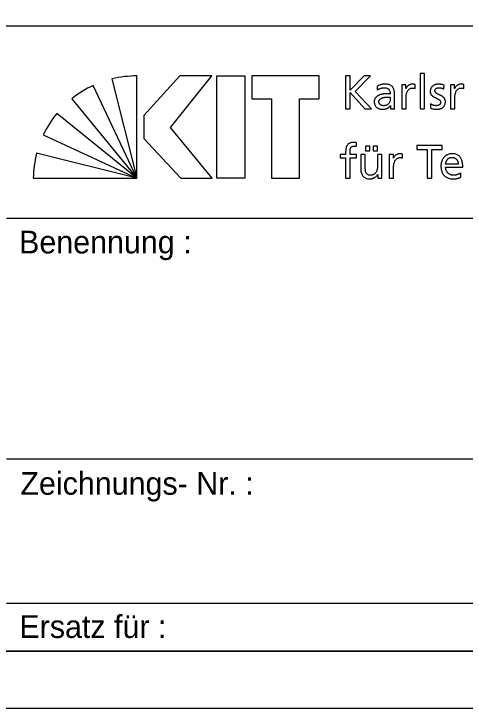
# Model space of a CAD drawing. Extents: x 0 to 29.7, y 0 to 21.
# Drawn here: x 27.516 to 28.508, y 0 to 1.526 of the extents above; entities that cross this region are included whole.
import ezdxf

# ---------------------------------------------------------------- set-up
doc = ezdxf.new("R2010")
doc.units = 0
doc.layers.add('90_Plankopf', color=7, linetype='Continuous')

msp = doc.modelspace()

# ---------------------------------------------------------------- linework, layer by layer
at = {"layer": '90_Plankopf'}
for p, q in [((25.153, 1.4998), (29.6, 1.4998)), ((25.153, 1.4998), (29.6, 1.4998)), ((27.787, 1.1647), (27.787, 1.3896)), ((28.2452, 1.3897), (28.2452, 1.3176)), ((27.7319, 1.3833), (27.787, 1.1647)), ((27.787, 1.1647), (27.6908, 1.3688)), ((28.3145, 1.3665), (28.315, 1.3583)), ((28.3982, 1.3621), (28.3982, 1.3708)), ((28.4614, 1.361), (28.4622, 1.3694)), ((28.5053, 1.3621), (28.5053, 1.3708)), ((28.353, 1.328), (28.353, 1.3497)), ((27.6436, 1.3396), (27.787, 1.1647)), ((28.3433, 1.3427), (28.3433, 1.3381)), ((28.4324, 1.328), (28.4319, 1.3193)), ((28.2452, 1.3176), (28.2556, 1.3176)), ((28.2876, 1.3176), (28.3027, 1.3176)), ((27.787, 1.1647), (27.6108, 1.3071)), ((27.581, 1.2603), (27.787, 1.1647)), ((28.2693, 1.2348), (28.2697, 1.2427)), ((27.787, 1.1647), (27.5664, 1.2197)), ((28.3707, 1.2091), (28.3707, 1.2178)), ((28.4927, 1.196), (28.4654, 1.196)), ((28.4654, 1.1888), (28.503, 1.1888)), ((28.4989, 1.1668), (28.4989, 1.1765)), ((27.5591, 1.1647), (27.787, 1.1647)), ((27.5, 1.0768), (29.6, 1.0768)), ((27.5, 0.548), (29.6, 0.548)), ((27.5, 0.2308), (29.6, 0.2308)), ((29.6, 0.125), (25.153, 0.125)), ((25.445, 0.125), (29.6, 0.125)), ((25.445, 0.125), (29.6, 0.125))]:
    msp.add_line(p, q, dxfattribs=at)
for points in [[(0, 0), (29.725, 0), (29.725, 21.025), (0, 21.025)], [(0.625, 0.125), (29.6, 0.125), (29.6, 20.9), (0.625, 20.9)], [(27.9517, 1.3897), (27.8809, 1.3897), (27.8018, 1.3025), (27.8018, 1.2523), (27.8834, 1.1647), (27.9521, 1.1647), (27.8606, 1.2766)], [(28.0243, 1.3897), (28.0243, 1.1647), (27.9625, 1.1647), (27.9625, 1.3897)], [(28.0391, 1.3897), (28.0391, 1.339), (28.0825, 1.339), (28.0825, 1.1647), (28.1443, 1.1647), (28.1443, 1.339), (28.1877, 1.339), (28.1877, 1.3897)]]:
    msp.add_lwpolyline(points, close=True, dxfattribs=at)
for points in [[(28.3027, 1.3176), (28.2662, 1.3556), (28.3, 1.3897), (28.2863, 1.3897), (28.2556, 1.358), (28.2556, 1.3897), (28.2452, 1.3897)], [(28.4095, 1.3176), (28.4192, 1.3176), (28.4192, 1.395), (28.4095, 1.395), (28.4095, 1.3176)], [(28.378, 1.3621), (28.3778, 1.3621), (28.3778, 1.3703), (28.3688, 1.3703), (28.3688, 1.3176), (28.3785, 1.3176), (28.3785, 1.3416)], [(28.4852, 1.3621), (28.485, 1.3621), (28.485, 1.3703), (28.4759, 1.3703), (28.4759, 1.3176), (28.4856, 1.3176), (28.4856, 1.3416)], [(28.2556, 1.3176), (28.2556, 1.3529), (28.2876, 1.3176)], [(28.3441, 1.3245), (28.3443, 1.3245), (28.3443, 1.3176), (28.3534, 1.3176)], [(28.4248, 1.1647), (28.4351, 1.1647), (28.4351, 1.2276), (28.4575, 1.2276), (28.4575, 1.2367), (28.4024, 1.2367), (28.4024, 1.2276), (28.4248, 1.2276), (28.4248, 1.1647)], [(28.2456, 1.2221), (28.2456, 1.2173), (28.2332, 1.2173), (28.2332, 1.2094), (28.2456, 1.2094), (28.2456, 1.1647), (28.2553, 1.1647), (28.2553, 1.2094), (28.2692, 1.2094), (28.2692, 1.2173), (28.2553, 1.2173), (28.2553, 1.223)], [(28.2889, 1.2356), (28.2889, 1.2253), (28.2986, 1.2253), (28.2986, 1.2356), (28.2889, 1.2356)], [(28.3058, 1.2356), (28.3058, 1.2253), (28.3155, 1.2253), (28.3155, 1.2356), (28.3058, 1.2356)], [(28.2885, 1.19), (28.2885, 1.2173), (28.2788, 1.2173), (28.2788, 1.186)], [(28.3254, 1.1647), (28.3254, 1.2173), (28.3157, 1.2173), (28.3157, 1.1929)], [(28.3506, 1.2091), (28.3504, 1.2091), (28.3504, 1.2173), (28.3413, 1.2173), (28.3413, 1.1647), (28.351, 1.1647), (28.351, 1.1886)], [(28.3158, 1.173), (28.316, 1.173), (28.316, 1.1647), (28.3254, 1.1647)]]:
    msp.add_lwpolyline(points, dxfattribs=at)
for centre, start, end in [((27.7862, 1.1514), 89.8053, 103.1895), ((27.7915, 1.1529), 115.0126, 128.3968), ((27.7954, 1.1566), 140.7898, 154.174), ((27.7973, 1.1609), 165.7222, 179.1064)]:
    msp.add_arc(centre, 0.2382, start, end, dxfattribs=at)
for points in [[(28.353, 1.3497), (28.353, 1.3545), (28.3523, 1.3585), (28.3508, 1.3617), (28.3494, 1.365), (28.3471, 1.3674), (28.344, 1.369), (28.3409, 1.3707), (28.3368, 1.3715), (28.3318, 1.3715), (28.3285, 1.3715), (28.3253, 1.371), (28.3224, 1.3701), (28.3195, 1.3692), (28.3169, 1.368), (28.3145, 1.3665)], [(28.315, 1.3583), (28.3163, 1.3594), (28.3178, 1.3604), (28.3195, 1.3611), (28.3211, 1.362), (28.3229, 1.3626), (28.3247, 1.363), (28.3266, 1.3634), (28.3284, 1.3637), (28.3303, 1.3637), (28.3335, 1.3637), (28.336, 1.3631), (28.3379, 1.3621), (28.3399, 1.3611), (28.3412, 1.3596), (28.342, 1.3575), (28.3429, 1.3555), (28.3433, 1.353), (28.3433, 1.3499)], [(28.3982, 1.3708), (28.3975, 1.3709), (28.3968, 1.371), (28.3962, 1.3712), (28.3956, 1.3713), (28.3949, 1.3713), (28.3942, 1.3714), (28.3935, 1.3715), (28.3927, 1.3715), (28.3918, 1.3715), (28.3899, 1.3715), (28.3881, 1.3711), (28.3863, 1.3703), (28.3845, 1.3695), (28.3829, 1.3684), (28.3815, 1.367), (28.3801, 1.3656), (28.3789, 1.3639), (28.378, 1.3621)], [(28.3785, 1.3416), (28.3785, 1.346), (28.3791, 1.3498), (28.3802, 1.353), (28.3814, 1.3562), (28.3831, 1.3587), (28.3852, 1.3604), (28.3874, 1.3621), (28.3899, 1.363), (28.3928, 1.363), (28.3936, 1.3631), (28.3945, 1.363), (28.3954, 1.3629), (28.3964, 1.3627), (28.3973, 1.3625), (28.3982, 1.3621)], [(28.4622, 1.3694), (28.4604, 1.37), (28.4584, 1.3705), (28.4565, 1.3709), (28.4545, 1.3713), (28.4524, 1.3715), (28.4502, 1.3715), (28.4476, 1.3715), (28.4451, 1.3712), (28.4429, 1.3705), (28.4406, 1.3698), (28.4387, 1.3688), (28.437, 1.3675), (28.4353, 1.3662), (28.434, 1.3645), (28.433, 1.3625), (28.4321, 1.3604), (28.4316, 1.358), (28.4316, 1.3553), (28.4316, 1.3532), (28.4321, 1.3514), (28.4329, 1.3498), (28.4337, 1.3483), (28.4348, 1.347), (28.4361, 1.3459), (28.4375, 1.3447), (28.439, 1.3437), (28.4406, 1.3429), (28.4422, 1.342), (28.4438, 1.3412), (28.4454, 1.3404), (28.4471, 1.3397), (28.4485, 1.3389), (28.4499, 1.338), (28.4512, 1.3373), (28.4523, 1.3363), (28.4532, 1.3353), (28.454, 1.3343), (28.4544, 1.3331), (28.4544, 1.3318), (28.4544, 1.3304), (28.4541, 1.3292), (28.4535, 1.3282), (28.4529, 1.3272), (28.4521, 1.3265), (28.4511, 1.3259), (28.4501, 1.3253), (28.4491, 1.3249), (28.4479, 1.3246), (28.4468, 1.3244), (28.4456, 1.3242), (28.4445, 1.3242), (28.4435, 1.3242), (28.4424, 1.3244), (28.441, 1.3247), (28.4396, 1.3249), (28.4381, 1.3253), (28.4366, 1.3259), (28.4351, 1.3265), (28.4337, 1.3271), (28.4324, 1.328)], [(28.4319, 1.3193), (28.4342, 1.3181), (28.4365, 1.3174), (28.4389, 1.317), (28.4414, 1.3166), (28.4439, 1.3164), (28.4464, 1.3164), (28.4487, 1.3164), (28.451, 1.3167), (28.4532, 1.3174), (28.4554, 1.318), (28.4573, 1.3191), (28.4591, 1.3204), (28.4608, 1.3217), (28.4622, 1.3234), (28.4632, 1.3255), (28.4642, 1.3276), (28.4647, 1.33), (28.4647, 1.3328), (28.4647, 1.3352), (28.4643, 1.3372), (28.4635, 1.3389), (28.4626, 1.3406), (28.4616, 1.342), (28.4602, 1.3431), (28.4589, 1.3443), (28.4574, 1.3453), (28.4557, 1.3461), (28.4541, 1.3469), (28.4525, 1.3477), (28.4509, 1.3484), (28.4493, 1.3491), (28.4478, 1.3499), (28.4464, 1.3507), (28.4451, 1.3515), (28.444, 1.3524), (28.4432, 1.3534), (28.4424, 1.3545), (28.4419, 1.3557), (28.4419, 1.3573), (28.4419, 1.3587), (28.4424, 1.3599), (28.4432, 1.3609), (28.4441, 1.3618), (28.4452, 1.3625), (28.4466, 1.363), (28.448, 1.3634), (28.4495, 1.3637), (28.4512, 1.3637), (28.4518, 1.3637), (28.4526, 1.3636), (28.4535, 1.3634), (28.4544, 1.3633), (28.4553, 1.3631), (28.4564, 1.3628), (28.4574, 1.3626), (28.4583, 1.3623), (28.4592, 1.362), (28.4601, 1.3616), (28.4609, 1.3613), (28.4614, 1.361)], [(28.5053, 1.3708), (28.5046, 1.3709), (28.504, 1.371), (28.5034, 1.3712), (28.5027, 1.3713), (28.5021, 1.3713), (28.5014, 1.3714), (28.5007, 1.3715), (28.4998, 1.3715), (28.4989, 1.3715), (28.497, 1.3715), (28.4952, 1.3711), (28.4934, 1.3703), (28.4917, 1.3695), (28.4901, 1.3684), (28.4886, 1.367), (28.4872, 1.3656), (28.486, 1.3639), (28.4852, 1.3621)], [(28.4856, 1.3416), (28.4856, 1.346), (28.4862, 1.3498), (28.4874, 1.353), (28.4886, 1.3562), (28.4902, 1.3587), (28.4923, 1.3604), (28.4945, 1.3621), (28.497, 1.363), (28.4999, 1.363), (28.5008, 1.3631), (28.5016, 1.363), (28.5026, 1.3629), (28.5035, 1.3627), (28.5044, 1.3625), (28.5053, 1.3621)], [(28.3433, 1.3499), (28.342, 1.35), (28.3408, 1.3501), (28.3397, 1.3501), (28.3386, 1.3501), (28.3376, 1.3501), (28.3365, 1.3501), (28.3354, 1.3501), (28.3342, 1.3501), (28.3329, 1.3501), (28.3309, 1.3501), (28.3288, 1.35), (28.3266, 1.3496), (28.3243, 1.3492), (28.3221, 1.3487), (28.32, 1.3478), (28.3179, 1.347), (28.316, 1.346), (28.3142, 1.3446), (28.3125, 1.3433), (28.3111, 1.3416), (28.3101, 1.3397), (28.309, 1.3377), (28.3085, 1.3354), (28.3085, 1.3328), (28.3085, 1.329), (28.3094, 1.3259), (28.311, 1.3235), (28.3126, 1.3211), (28.3149, 1.3193), (28.3177, 1.3181), (28.3206, 1.317), (28.324, 1.3164), (28.3278, 1.3164), (28.33, 1.3164), (28.332, 1.3167), (28.3338, 1.3172), (28.3355, 1.3177), (28.3371, 1.3184), (28.3384, 1.3192), (28.3398, 1.32), (28.3409, 1.3209), (28.3418, 1.3218), (28.3428, 1.3228), (28.3435, 1.3236), (28.3441, 1.3245)], [(28.3433, 1.3381), (28.3433, 1.3354), (28.3427, 1.3331), (28.3416, 1.331), (28.3405, 1.3289), (28.3388, 1.3273), (28.3367, 1.3261), (28.3345, 1.3249), (28.3318, 1.3243), (28.3286, 1.3242), (28.3275, 1.3242), (28.3264, 1.3244), (28.3252, 1.3248), (28.3241, 1.3252), (28.323, 1.3257), (28.322, 1.3264), (28.3211, 1.3272), (28.3203, 1.3281), (28.3197, 1.3291), (28.3191, 1.3302), (28.3188, 1.3314), (28.3188, 1.3328), (28.3188, 1.3347), (28.3193, 1.3362), (28.3202, 1.3374), (28.3211, 1.3387), (28.3223, 1.3396), (28.3237, 1.3404), (28.3252, 1.3411), (28.3267, 1.3417), (28.3284, 1.342), (28.33, 1.3424), (28.3316, 1.3426), (28.3332, 1.3428), (28.3347, 1.3429), (28.336, 1.3429), (28.3371, 1.3429), (28.3381, 1.3429), (28.3391, 1.3429), (28.3402, 1.3428), (28.3412, 1.3428), (28.3422, 1.3427), (28.3433, 1.3427)], [(28.3534, 1.3176), (28.3533, 1.3181), (28.3532, 1.3188), (28.3532, 1.3197), (28.3531, 1.3205), (28.3531, 1.3216), (28.353, 1.323), (28.353, 1.3243), (28.353, 1.326), (28.353, 1.328)], [(28.2697, 1.2427), (28.2688, 1.2428), (28.2678, 1.243), (28.2667, 1.2431), (28.2656, 1.2432), (28.2645, 1.2433), (28.2632, 1.2433), (28.2597, 1.2433), (28.2568, 1.2428), (28.2544, 1.2418), (28.2521, 1.2408), (28.2503, 1.2394), (28.2491, 1.2375), (28.2478, 1.2356), (28.2469, 1.2334), (28.2464, 1.2308), (28.2458, 1.2282), (28.2456, 1.2253), (28.2456, 1.2221)], [(28.2553, 1.223), (28.2553, 1.2247), (28.2554, 1.2264), (28.2556, 1.2279), (28.2558, 1.2294), (28.2562, 1.2307), (28.2569, 1.2319), (28.2575, 1.233), (28.2585, 1.2339), (28.2597, 1.2345), (28.261, 1.2351), (28.2626, 1.2354), (28.2647, 1.2354), (28.2655, 1.2354), (28.2664, 1.2354), (28.2672, 1.2353), (28.268, 1.2352), (28.2688, 1.235), (28.2693, 1.2348)], [(28.3707, 1.2178), (28.37, 1.2179), (28.3693, 1.2181), (28.3688, 1.2182), (28.3681, 1.2183), (28.3675, 1.2184), (28.3667, 1.2184), (28.3661, 1.2185), (28.3652, 1.2185), (28.3643, 1.2185), (28.3624, 1.2185), (28.3606, 1.2181), (28.3588, 1.2173), (28.3571, 1.2165), (28.3555, 1.2154), (28.354, 1.214), (28.3526, 1.2126), (28.3514, 1.211), (28.3506, 1.2091)], [(28.351, 1.1886), (28.351, 1.193), (28.3516, 1.1968), (28.3528, 1.2), (28.3539, 1.2032), (28.3556, 1.2057), (28.3577, 1.2074), (28.3599, 1.2092), (28.3624, 1.21), (28.3653, 1.21), (28.3662, 1.2101), (28.367, 1.21), (28.368, 1.2099), (28.3689, 1.2097), (28.3698, 1.2095), (28.3707, 1.2091)], [(28.503, 1.1888), (28.503, 1.1931), (28.5026, 1.197), (28.5018, 1.2006), (28.501, 1.2042), (28.4997, 1.2073), (28.4979, 1.21), (28.4961, 1.2127), (28.4938, 1.2148), (28.4908, 1.2162), (28.4878, 1.2177), (28.4841, 1.2185), (28.4797, 1.2185), (28.476, 1.2185), (28.4726, 1.2178), (28.4696, 1.2166), (28.4666, 1.2152), (28.464, 1.2134), (28.4618, 1.2111), (28.4597, 1.2087), (28.458, 1.2059), (28.4569, 1.2026), (28.4557, 1.1994), (28.4551, 1.1958), (28.4551, 1.1919), (28.4551, 1.1876), (28.4556, 1.1837), (28.4567, 1.1802), (28.4578, 1.1767), (28.4595, 1.1737), (28.4617, 1.1712), (28.4639, 1.1687), (28.4668, 1.1668), (28.4702, 1.1655), (28.4736, 1.1641), (28.4777, 1.1634), (28.4823, 1.1634), (28.4852, 1.1634), (28.4876, 1.1636), (28.4897, 1.164), (28.4917, 1.1644), (28.4934, 1.1648), (28.4949, 1.1653), (28.4964, 1.1659), (28.4977, 1.1664), (28.4989, 1.1668)], [(28.4654, 1.196), (28.4656, 1.1977), (28.466, 1.1995), (28.4666, 1.2012), (28.4672, 1.2029), (28.4681, 1.2045), (28.4692, 1.2059), (28.4703, 1.2073), (28.4717, 1.2085), (28.4734, 1.2093), (28.4751, 1.2102), (28.4772, 1.2107), (28.4795, 1.2107), (28.4816, 1.2107), (28.4835, 1.2103), (28.4851, 1.2095), (28.4867, 1.2088), (28.4881, 1.2077), (28.4892, 1.2064), (28.4903, 1.205), (28.4912, 1.2035), (28.4918, 1.2017), (28.4924, 1.1999), (28.4927, 1.1981), (28.4927, 1.196)], [(28.3157, 1.1929), (28.3157, 1.1897), (28.3154, 1.1868), (28.3147, 1.1841), (28.3141, 1.1815), (28.3131, 1.1792), (28.3118, 1.1773), (28.3105, 1.1754), (28.3088, 1.1739), (28.3068, 1.1728), (28.3048, 1.1718), (28.3024, 1.1713), (28.2997, 1.1713), (28.2969, 1.1714), (28.2947, 1.1722), (28.293, 1.1736), (28.2914, 1.175), (28.2902, 1.1771), (28.2895, 1.1798), (28.2889, 1.1825), (28.2885, 1.1859), (28.2885, 1.19)], [(28.2788, 1.186), (28.2788, 1.1813), (28.2795, 1.1772), (28.2809, 1.1739), (28.2823, 1.1705), (28.2845, 1.1679), (28.2874, 1.1661), (28.2903, 1.1644), (28.294, 1.1634), (28.2986, 1.1634), (28.301, 1.1634), (28.3034, 1.1638), (28.3056, 1.1646), (28.3079, 1.1653), (28.3099, 1.1665), (28.3117, 1.1679), (28.3134, 1.1693), (28.3148, 1.171), (28.3158, 1.173)], [(28.4989, 1.1765), (28.4983, 1.176), (28.4975, 1.1755), (28.4963, 1.1749), (28.4952, 1.1743), (28.4939, 1.1737), (28.4924, 1.1732), (28.4909, 1.1726), (28.4893, 1.1722), (28.4876, 1.1718), (28.486, 1.1715), (28.4844, 1.1713), (28.4827, 1.1713), (28.4804, 1.1713), (28.4782, 1.1717), (28.4762, 1.1725), (28.4741, 1.1734), (28.4722, 1.1746), (28.4706, 1.1761), (28.469, 1.1777), (28.4677, 1.1795), (28.4668, 1.1817), (28.4659, 1.1838), (28.4654, 1.1862), (28.4654, 1.1888)]]:
    msp.add_open_spline(points, degree=3, dxfattribs=at)

# ---------------------------------------------------------------- texts
for s, p in [('Benennung :', (27.5278, 0.9995)), ('Zeichnungs- Nr. :', (27.5307, 0.469)), ('Ersatz für :', (27.5285, 0.1542))]:
    msp.add_text(s, height=0.05, dxfattribs=at).set_placement(p)

doc.saveas('drawing.dxf')
